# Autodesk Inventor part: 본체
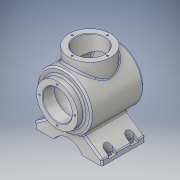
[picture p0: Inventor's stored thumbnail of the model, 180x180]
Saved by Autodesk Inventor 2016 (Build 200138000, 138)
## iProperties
Created: 2021-04
Part Number: 본체
Material: 알루미늄 6061
Document SubType Name: Modeling
Designer: pc-04
Density: 2.7 g/cm^3
Appearance: 알루미늄 - 평지
Mass: 1642.63 g
Surface Area: 1047.47 cm^2
Volume: 608.38 cm^3
Author: pc-04
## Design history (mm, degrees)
sketch "스케치1"
  geometry: L1 (0, 0)-(25.981, 0); L2 (62, 0)-(62, 10); L3 (62, 10)-(26.296, 35); L4 (26.296, 35)-(-26.296, 35); L5 (-26.296, 35)-(-62, 10); L6 (-62, 10)-(-62, 0); L7 (-62, 0)-(-25.981, 0); L8 (-25.981, 0)-(0, 0); L9 (25.981, 0)-(62, 0); A1 r 30 centre (0, -15) between (25.981, 0) and (-25.981, 0); 1 further point
  constraints: 18 end point, 4 collinear, 3 parallel, 2 horizontal, 2 perpendicular, 2 point on circle, 2 vertical alignment, 1 centre point, 1 midpoint, 1 point on line
  dimensions: "d0" = 124 distance between parallel lines of L2 L6; "d1" = 30 radius of A1; "d2" = 15 distance centre to line of A1 L1; "d3" = 10 distance from line of L7 L5.end; "d4" = 10 distance from line of L1 L2.end; "d5" = 55 deg angle of L5 L6; "d6" = 55 deg angle of L3 L2; "d22" = 35 distance between parallel lines of L9 L4
extrude "돌출1" new body sketch "스케치1" stored distance "d8" = 80; taper "d9" = 0 deg
sketch "스케치2"
  geometry: L1 (77, -60)-(77, 60); L2 (77, 60)-(115, 60); L3 (115, 60)-(115, 48); L4 (115, 48)-(127, 48); L5 (127, 48)-(127, -48.336); L6 (104, 60)-(104, 38); L7 (104, 38)-(117, 38); L8 (117, 38)-(117, -41.916); L9 (0, -40)-(0, 40) reference; L10 (0, 40)-(15, 40) reference; A1 r 113 centre (77, 53) between (77, -60) and (127, -48.336); A2 r 103 centre (77, 53) between (77, -50) and (117, -41.916); 1 further point
  constraints: 16 end point, 7 perpendicular, 4 point on circle, 3 point on line, 2 centre point, 1 vertical
  dimensions: "d10" = 100 diameter of L5 L1; "d11" = 76 diameter of L3 L1; "d12" = 120 distance of L1.start L1.end; "d13" = 103 radius of A2; "d14" = 113 radius of A1; "d15" = 12 distance between parallel lines of L4 L2; "d16" = 80 diameter of L8 L1; "d17" = 22 distance between parallel lines of L7 L2; "d18" = 77 distance between parallel lines of L9 L1; "d19" = 20 distance between parallel lines of L2 L10; "d20" = 54 diameter of L6 L1
revolve "회전1" sketch "스케치2" stored, may be unused: angle "d21" = 90 deg
sketch "스케치3"
  geometry: L1 (62, 0)-(25.981, 0) reference; L2 (0, 117)-(38, 117); L3 (38, 117)-(38, 142); L4 (38, 142)-(0, 142); L5 (0, 142)-(0, 117); 4 further points
  constraints: 8 end point, 2 parallel, 2 vertical alignment, 1 horizontal, 1 perpendicular, 1 other
  dimensions: "d29" = 142 distance between parallel lines of L1 L4; "d30" = 76 diameter of L3 L5; "d31" = 25 distance between parallel lines of L2 L4
revolve "회전3" sketch "스케치3" stored, may be unused: angle "d32" = 90 deg
sketch "스케치4"
  geometry: L1 (30, 117)-(38, 117) reference; L2 (38, 117)-(30, 117); L3 (30, 117)-(30, 109.496); L4 (30, 109.496)-(38, 109.496); L5 (38, 109.496)-(38, 117); L6 (0, -28.4)-(0, 170.4) reference; L7 (-38, 117)-(-30, 117); L8 (-30, 117)-(-30, 109.496); L9 (-30, 109.496)-(-38, 109.496); L10 (-38, 109.496)-(-38, 117); L11 (-38, 117)-(-30, 117) reference; A1 r 50 centre (0, 77) between (30, 117) and (38, 109.496) reference; 1 further point
  constraints: 16 end point, 4 parallel, 3 point on circle, 2 horizontal, 2 perpendicular, 1 point on line
  dimensions: "d33" = 8 distance between parallel lines of L5 L3; "d36" = 8 distance between parallel lines of L8 L10
revolve "회전4" stored, may be unused: angle "d34" = 90 deg
revolve "회전5" stored, may be unused: angle "d35" = 90 deg
revolve "회전6" stored, may be unused: angle "d37" = 90 deg
revolve "회전7" stored, may be unused: angle "d38" = 90 deg
hole "구멍1" diameter "d41" = 54; stored, may be unused: countersink angle "d45" = 90 deg, drill point angle "d47" = 0 deg; dims "d39" = 10, "d40" = 10, "d42" = 6, "d43" = 4, "d44" = 2, "d46" = 8
node "작업 평면2"
sketch "스케치5"
  geometry: L1 (-54, -27)-(-62, -27); L2 (-54, -13)-(-62, -13); L3 (-62, 40)-(-62, -40) reference; L4 (-26.694, -40)-(-62, -40) reference; C1 r 4.5 at (-54, -20); A1 r 7 centre (-54, -20) between (-54, -27) and (-54, -13); 1 further point
  constraints: 4 end point, 2 centre point, 2 horizontal, 2 point on circle, 2 point on line, 1 coincident, 1 parallel
  dimensions: "d49" = 14 diameter of A1; "d50" = 8 distance from line of L3 A1.centre; "d51" = 20 distance from line of A1.centre L4; "d52" = 8 distance of L1.start L1.end; "d53" = 9 diameter of C1
extrude "돌출2" cut sketch "스케치5" distance "d54" = 24; taper "d55" = 0 deg
extrude "돌출3" cut sketch "스케치5" stored distance "d56" = 24; taper "d57" = 0 deg
fillet "모깎기1" dims "d61" = 3
fillet "모깎기2" dims "d62" = 3
chamfer "모따기1" distance "d63" = 1; stored, may be unused: second distance "d64" = 2, angle "d65" = 45 deg
chamfer "모따기2" distance "d66" = 1; stored, may be unused: second distance "d67" = 2, angle "d68" = 45 deg
node "작업 평면6"
sketch "스케치8"
  geometry: L1 (50, 0)-(-50, 0); A1 r 50 centre (0, 0) between (50, 0) and (-50, 0) reference; 1 further point
  constraints: 2 end point, 2 horizontal, 2 point on circle
extrude "돌출6" join sketch "스케치8" distance "d79" = 5.5; taper "d80" = 0 deg
sketch "스케치9"
  geometry: C1 r 38 at (0, 0) reference; 2 further points
  constraints: 1 vertical alignment
  dimensions: "d81" = 32.5 distance of point (0, 32.5) C1.centre
hole "구멍2" sketch "스케치9" at (0, 32.5) diameter "d82" = 3.242; stored, may be unused: countersink angle "d86" = 90 deg, drill point angle "d88" = 118 deg; dims "d83" = 8, "d84" = 4, "d85" = 2, "d87" = 10
sketch "스케치10"
  geometry: 2 further points
  constraints: 1 vertical alignment
  dimensions: "d92" = 32.5 distance of point (0, 0) point (0, 32.5)
hole "구멍3" sketch "스케치10" at (0, 32.5) diameter "d93" = 3.242; stored, may be unused: countersink angle "d97" = 90 deg, drill point angle "d99" = 118 deg; dims "d94" = 8, "d95" = 4, "d96" = 2, "d98" = 10
node "솔리드1"
pattern_linear "직사각형 패턴1"
mirror "대칭1"
pattern_circular "원형 패턴1" dims angle "d90" = 360 deg
pattern_circular "원형 패턴2" dims angle "d101" = 360 deg
other parameters: "d78" = -115
